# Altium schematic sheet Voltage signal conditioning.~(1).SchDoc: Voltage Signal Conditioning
size 431 x 279 mm; Date: Not shown in title block; ApprovedBy: Not shown in title block; CheckedBy: Not shown in title block; Author: Not shown in title block; CompanyName: Not shown in title block; Engineer: Not shown in title block; Organization: Not shown in title block; Address1: Not shown in title block; Address2: Not shown in title block; Address3: Not shown in title block; Address4: Not shown in title block; DocumentNumber: 4; Revision: Use project parameter SCH_Rev; SheetNumber: 4; SheetTotal: 7; PageSetup: Record=PageOptions|CenterHorizontal=True|CenterVertical=True|PrintScale=1.00|XCorrection=1.00|YCorrection=1.00|PrintKind=0|BorderSize=5000000|LeftOffset=0|BottomOffset=0|Orientation=2|PaperLength=1000|PaperWidth=1000|Scale=100|PaperSource=15|PrintQuality=600|MediaType=1|DitherType=10|PaperKind=Letter|PrintScaleMode=1
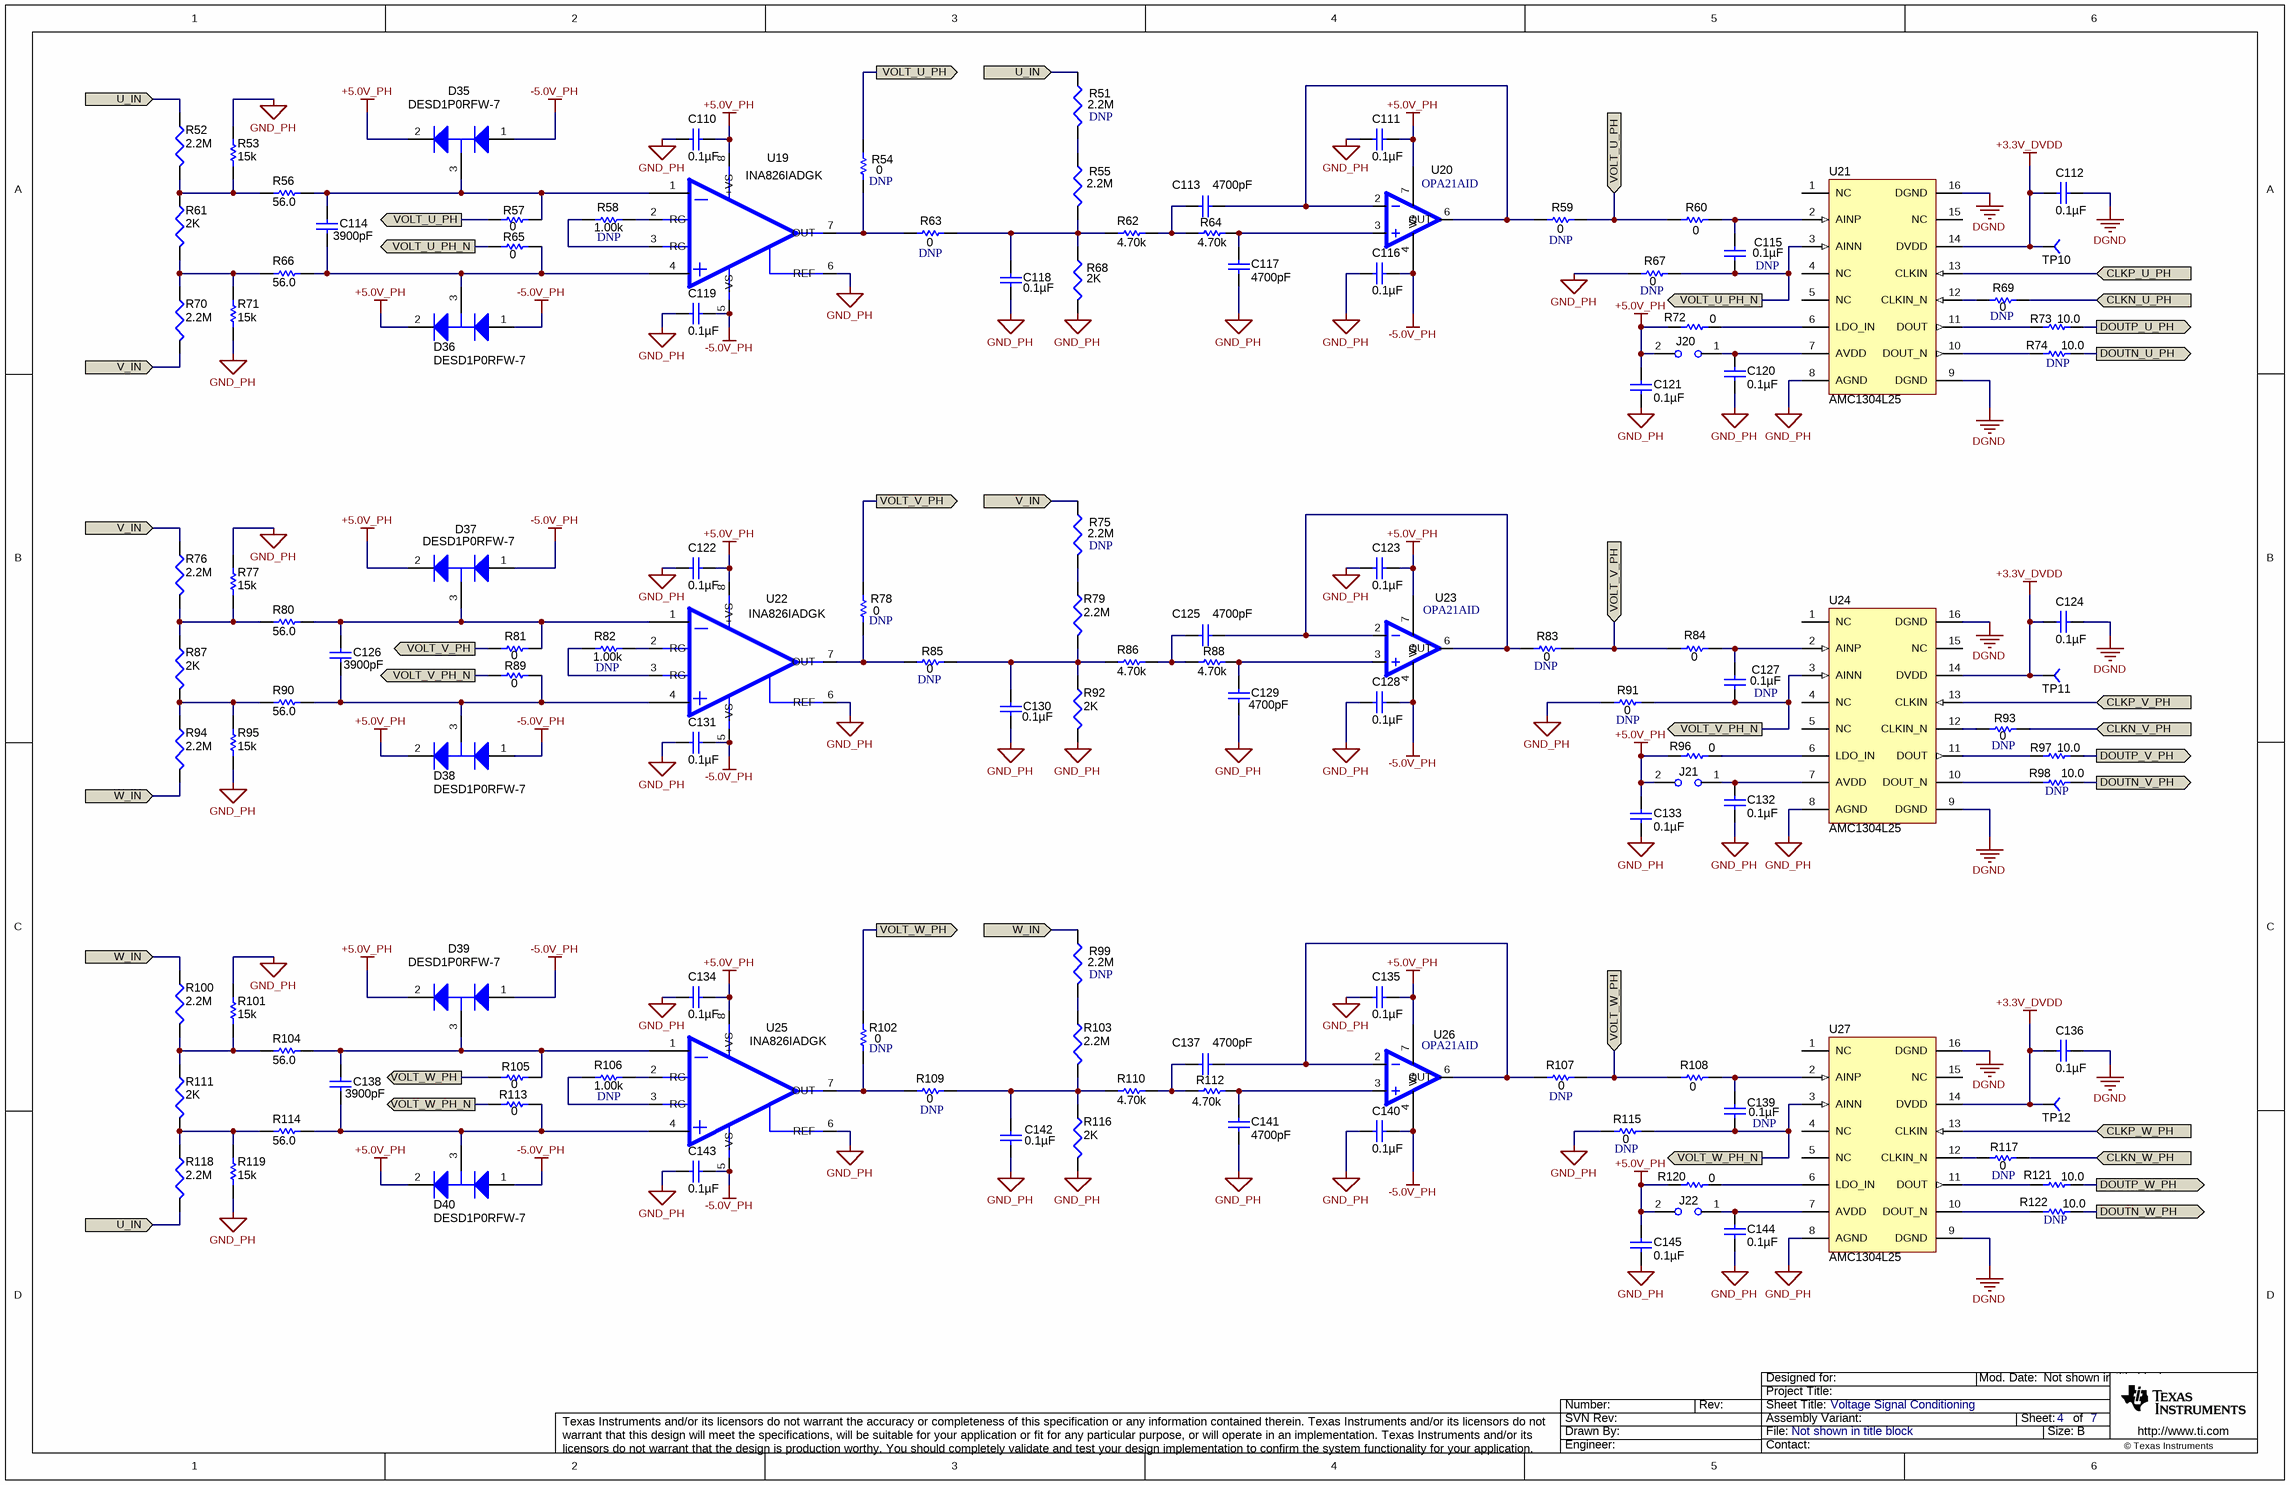
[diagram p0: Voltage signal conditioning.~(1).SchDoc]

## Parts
C110  ValueDisplayed: 0.1µF  [0603]
C111  ValueDisplayed: 0.1µF  [0603]
C112  ValueDisplayed: 0.1µF  [0603]
C113  ValueDisplayed: 4700pF  [0603]
C114  ValueDisplayed: 3900pF  [0603]  (hidden comment: C1608C0G1E392J)
C115  ValueDisplayed: 0.1µF  Not mounted: DNP  [0603]
C116  ValueDisplayed: 0.1µF  [0603]
C117  ValueDisplayed: 4700pF  [0603]
C118  ValueDisplayed: 0.1µF  [0603]
C119  ValueDisplayed: 0.1µF  [0603]
C120  ValueDisplayed: 0.1µF  [0603]
C121  ValueDisplayed: 0.1µF  [0603]
C122  ValueDisplayed: 0.1µF  [0603]
C123  ValueDisplayed: 0.1µF  [0603]
C124  ValueDisplayed: 0.1µF  [0603]
C125  ValueDisplayed: 4700pF  [0603]
C126  ValueDisplayed: 3900pF  [0603]  (hidden comment: C1608C0G1E392J)
C127  ValueDisplayed: 0.1µF  Not mounted: DNP  [0603]
C128  ValueDisplayed: 0.1µF  [0603]
C129  ValueDisplayed: 4700pF  [0603]
C130  ValueDisplayed: 0.1µF  [0603]
C131  ValueDisplayed: 0.1µF  [0603]
C132  ValueDisplayed: 0.1µF  [0603]
C133  ValueDisplayed: 0.1µF  [0603]
C134  ValueDisplayed: 0.1µF  [0603]
C135  ValueDisplayed: 0.1µF  [0603]
C136  ValueDisplayed: 0.1µF  [0603]
C137  ValueDisplayed: 4700pF  [0603]
C138  ValueDisplayed: 3900pF  [0603]  (hidden comment: C1608C0G1E392J)
C139  ValueDisplayed: 0.1µF  Not mounted: DNP  [0603]
C140  ValueDisplayed: 0.1µF  [0603]
C141  ValueDisplayed: 4700pF  [0603]
C142  ValueDisplayed: 0.1µF  [0603]
C143  ValueDisplayed: 0.1µF  [0603]
C144  ValueDisplayed: 0.1µF  [0603]
C145  ValueDisplayed: 0.1µF  [0603]
D35  DESD1P0RFW-7  [SOT-323]
D36  DESD1P0RFW-7  [SOT-323]
D37  DESD1P0RFW-7  [SOT-323]
D38  DESD1P0RFW-7  [SOT-323]
D39  DESD1P0RFW-7  [SOT-323]
D40  DESD1P0RFW-7  [SOT-323]
J20  (no value)  [HDR100_1X2]
J21  (no value)  [HDR100_1X2]
J22  (no value)  [HDR100_1X2]
R51  value 2.2M  Not mounted: DNP  [1210M]
R52  value 2.2M  [1210M]
R53  value 15k  [0603]
R54  value 0  Not mounted: DNP  [0603]
R55  value 2.2M  [1210M]
R56  value 56.0  [0603]  (hidden comment: RC0603FR-0756RL)
R57  value 0  [0603]
R58  value 1.00k  Not mounted: DNP  [0603]
R59  value 0  Not mounted: DNP  [0603]
R60  value 0  [0603]  (hidden comment: CRCW06030000Z0EA)
R61  value 2K  [1210M]
R62  value 4.70k  [0603]
R63  value 0  Not mounted: DNP  [0603]
R64  value 4.70k  [0603]
R65  value 0  [0603]
R66  value 56.0  [0603]  (hidden comment: RC0603FR-0756RL)
R67  value 0  Not mounted: DNP  [0603]
R68  value 2K  [1210M]
R69  value 0  Not mounted: DNP  [0603]
R70  value 2.2M  [1210M]
R71  value 15k  [0603]
R72  value 0  [0603]
R73  value 10.0  [0603]
R74  value 10.0  Not mounted: DNP  [0603]
R75  value 2.2M  Not mounted: DNP  [1210M]
R76  value 2.2M  [1210M]
R77  value 15k  [0603]
R78  value 0  Not mounted: DNP  [0603]
R79  value 2.2M  [1210M]
R80  value 56.0  [0603]  (hidden comment: RC0603FR-0756RL)
R81  value 0  [0603]
R82  value 1.00k  Not mounted: DNP  [0603]
R83  value 0  Not mounted: DNP  [0603]
R84  value 0  [0603]  (hidden comment: CRCW06030000Z0EA)
R85  value 0  Not mounted: DNP  [0603]
R86  value 4.70k  [0603]
R87  value 2K  [1210M]
R88  value 4.70k  [0603]
R89  value 0  [0603]
R90  value 56.0  [0603]  (hidden comment: RC0603FR-0756RL)
R91  value 0  Not mounted: DNP  [0603]
R92  value 2K  [1210M]
R93  value 0  Not mounted: DNP  [0603]
R94  value 2.2M  [1210M]
R95  value 15k  [0603]
R96  value 0  [0603]
R97  value 10.0  [0603]
R98  value 10.0  Not mounted: DNP  [0603]
R99  value 2.2M  Not mounted: DNP  [1210M]
R100  value 2.2M  [1210M]
R101  value 15k  [0603]
R102  value 0  Not mounted: DNP  [0603]
R103  value 2.2M  [1210M]
R104  value 56.0  [0603]  (hidden comment: RC0603FR-0756RL)
R105  value 0  [0603]
R106  value 1.00k  Not mounted: DNP  [0603]
R107  value 0  Not mounted: DNP  [0603]
R108  value 0  [0603]  (hidden comment: CRCW06030000Z0EA)
R109  value 0  Not mounted: DNP  [0603]
R110  value 4.70k  [0603]
R111  value 2K  [1210M]
R112  value 4.70k  [0603]
R113  value 0  [0603]
R114  value 56.0  [0603]  (hidden comment: RC0603FR-0756RL)
R115  value 0  Not mounted: DNP  [0603]
R116  value 2K  [1210M]
R117  value 0  Not mounted: DNP  [0603]
R118  value 2.2M  [1210M]
R119  value 15k  [0603]
R120  value 0  [0603]
R121  value 10.0  [0603]
R122  value 10.0  Not mounted: DNP  [0603]
TP10  (no value)  [TP-040_RND]
TP11  (no value)  [TP-040_RND]
TP12  (no value)  [TP-040_RND]
U19  INA826IADGK  [DGK8]
U20  OPA21AID  [SO8]
U21  AMC1304L25  [DW0016A_N]
U22  INA826IADGK  [DGK8]
U23  OPA21AID  [SO8]
U24  AMC1304L25  [DW0016A_N]
U25  INA826IADGK  [DGK8]
U26  OPA21AID  [SO8]
U27  AMC1304L25  [DW0016A_N]

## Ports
CLKN_U_PH (in), CLKN_V_PH (in), CLKN_W_PH (in), CLKP_U_PH (in), CLKP_V_PH (in), CLKP_W_PH (in), DOUTN_U_PH (out), DOUTN_V_PH (out), DOUTN_W_PH (out), DOUTP_U_PH (out), DOUTP_V_PH (out), DOUTP_W_PH (out), U_IN, V_IN, VOLT_U_PH (in), VOLT_U_PH (out), VOLT_U_PH_N (out), VOLT_V_PH (in), VOLT_V_PH (out), VOLT_V_PH_N (out), VOLT_W_PH (in), VOLT_W_PH (out), VOLT_W_PH_N (out), W_IN

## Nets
+3.3V_DVDD: C112.2 C124.2 C136.2 TP10.1 TP11.1 TP12.1 U21.14(DVDD) U24.14(DVDD) U27.14(DVDD)
+5.0V_PH: C110.2 C111.2 C121.1 C122.2 C123.2 C133.1 C134.2 C135.2 C145.1 D35.2(K) D36.2(K) D37.2(K) D38.2(K) D39.2(K) D40.2(K) J20.2 J21.2 J22.2 R72.1 R96.1 R120.1 U19.8(+VS) U20.7(V+) U22.8(+VS) U23.7(V+) U25.8(+VS) U26.7(V+)
-5.0V_PH: C116.2 C119.2 C128.2 C131.2 C140.2 C143.2 D35.1(A) D36.1(A) D37.1(A) D38.1(A) D39.1(A) D40.1(A) U19.5(-VS) U20.4(V-) U22.5(-VS) U23.4(V-) U25.5(-VS) U26.4(V-)
DGND: C112.1 C124.1 C136.1 U21.9(DGND) U21.16(DGND) U24.9(DGND) U24.16(DGND) U27.9(DGND) U27.16(DGND)
GND_PH: C110.1 C111.1 C116.1 C117.2 C118.1 C119.1 C120.2 C121.2 C122.1 C123.1 C128.1 C129.2 C130.1 C131.1 C132.2 C133.2 C134.1 C135.1 C140.1 C141.2 C142.1 C143.1 C144.2 C145.2 R53.2 R67.2 R68.2 R71.1 R77.2 R91.2 R92.2 R95.1 R101.2 R115.2 R116.2 R119.1 U19.6(REF) U21.8(AGND) U22.6(REF) U24.8(AGND) U25.6(REF) U27.8(AGND)
CLKN_U_PH: R69.2 ; port CLKN_U_PH
CLKN_V_PH: R93.2 ; port CLKN_V_PH
CLKN_W_PH: R117.2 ; port CLKN_W_PH
CLKP_U_PH: U21.13(CLKIN) ; port CLKP_U_PH
CLKP_V_PH: U24.13(CLKIN) ; port CLKP_V_PH
CLKP_W_PH: U27.13(CLKIN) ; port CLKP_W_PH
DOUTN_U_PH: R74.2 ; port DOUTN_U_PH
DOUTN_V_PH: R98.2 ; port DOUTN_V_PH
DOUTN_W_PH: R122.2 ; port DOUTN_W_PH
DOUTP_U_PH: R73.2 ; port DOUTP_U_PH
DOUTP_V_PH: R97.2 ; port DOUTP_V_PH
DOUTP_W_PH: R121.2 ; port DOUTP_W_PH
U_IN: R51.1 R52.1 R118.2 ; port U_IN
V_IN: R70.2 R75.1 R76.1 ; port V_IN
VOLT_U_PH: R54.2 R57.2 R59.2 R60.1 ; port VOLT_U_PH
VOLT_U_PH_N: C115.2 R65.2 R67.1 U21.3(AINN) ; port VOLT_U_PH_N
VOLT_V_PH: R78.2 R81.2 R83.2 R84.1 ; port VOLT_V_PH
VOLT_V_PH_N: C127.2 R89.2 R91.1 U24.3(AINN) ; port VOLT_V_PH_N
VOLT_W_PH: R102.2 R105.2 R107.2 R108.1 ; port VOLT_W_PH
VOLT_W_PH_N: C139.2 R113.2 R115.1 U27.3(AINN) ; port VOLT_W_PH_N
W_IN: R94.2 R99.1 R100.1 ; port W_IN
NetC113_1: C113.1 R62.2 R64.1
NetC113_2: C113.2 R59.1 U20.2 U20.6(OUT)
NetC114_1: C114.1 D35.3(C) R56.2 R57.1 U19.1
NetC114_2: C114.2 D36.3(C) R65.1 R66.2 U19.4
NetC115_1: C115.1 R60.2 U21.2(AINP)
NetC117_1: C117.1 R64.2 U20.3
NetC118_2: C118.2 R55.2 R62.1 R63.2 R68.1
NetC120_1: C120.1 J20.1 U21.7(AVDD)
NetC125_1: C125.1 R86.2 R88.1
NetC125_2: C125.2 R83.1 U23.2 U23.6(OUT)
NetC126_1: C126.1 D37.3(C) R80.2 R81.1 U22.1
NetC126_2: C126.2 D38.3(C) R89.1 R90.2 U22.4
NetC127_1: C127.1 R84.2 U24.2(AINP)
NetC129_1: C129.1 R88.2 U23.3
NetC130_2: C130.2 R79.2 R85.2 R86.1 R92.1
NetC132_1: C132.1 J21.1 U24.7(AVDD)
NetC137_1: C137.1 R110.2 R112.1
NetC137_2: C137.2 R107.1 U26.2 U26.6(OUT)
NetC138_1: C138.1 D39.3(C) R104.2 R105.1 U25.1
NetC138_2: C138.2 D40.3(C) R113.1 R114.2 U25.4
NetC139_1: C139.1 R108.2 U27.2(AINP)
NetC141_1: C141.1 R112.2 U26.3
NetC142_2: C142.2 R103.2 R109.2 R110.1 R116.1
NetC144_1: C144.1 J22.1 U27.7(AVDD)
NetR51_2: R51.2 R55.1
NetR52_2: R52.2 R53.1 R56.1 R61.1
NetR54_1: R54.1 R63.1 U19.7(OUT)
NetR58_1: R58.1 U19.3(RG)
NetR58_2: R58.2 U19.2(RG)
NetR61_2: R61.2 R66.1 R70.1 R71.2
NetR69_1: R69.1 U21.12(CLKIN_N)
NetR72_2: R72.2 U21.6(LDO_IN)
NetR73_1: R73.1 U21.11(DOUT)
NetR74_1: R74.1 U21.10(DOUT_N)
NetR75_2: R75.2 R79.1
NetR76_2: R76.2 R77.1 R80.1 R87.1
NetR78_1: R78.1 R85.1 U22.7(OUT)
NetR82_1: R82.1 U22.3(RG)
NetR82_2: R82.2 U22.2(RG)
NetR87_2: R87.2 R90.1 R94.1 R95.2
NetR93_1: R93.1 U24.12(CLKIN_N)
NetR96_2: R96.2 U24.6(LDO_IN)
NetR97_1: R97.1 U24.11(DOUT)
NetR98_1: R98.1 U24.10(DOUT_N)
NetR99_2: R99.2 R103.1
NetR100_2: R100.2 R101.1 R104.1 R111.1
NetR102_1: R102.1 R109.1 U25.7(OUT)
NetR106_1: R106.1 U25.3(RG)
NetR106_2: R106.2 U25.2(RG)
NetR111_2: R111.2 R114.1 R118.1 R119.2
NetR117_1: R117.1 U27.12(CLKIN_N)
NetR120_2: R120.2 U27.6(LDO_IN)
NetR121_1: R121.1 U27.11(DOUT)
NetR122_1: R122.1 U27.10(DOUT_N)

Not connected (* = marked no-connect by the designer): U21 1(NC) 4(NC) 5(NC) 15(NC); U24 1(NC) 4(NC) 5(NC) 15(NC); U27 1(NC) 4(NC) 5(NC) 15(NC)

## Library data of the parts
C110 C111 C115 C116 C118-C123 C127 C128 C130-C135 C139 C140 C142-C145 = C0603C104K5RACTU: CAP, CERM, 0.1uF, 50V, +/-10%, X7R, 0603; Manufacturer: Kemet; Polarized: N; CompType: Capacitor; U/M: EA; Cap_F: 0.0000001; Tolerance_%: 10; Value1: Unknown; VDC_V: 50; TaMin_C: -55; TaMax_C: 125
C112 C124 C136 = 06033C104JAT2A: CAP, CERM, 0.1uF, 25V, +/-5%, X7R, 0603; Manufacturer: AVX; Polarized: N; CompType: Capacitor; U/M: EA; Cap_F: 0.0000001; Tolerance_%: 5; ESR_Ohm: 0.05; Value1: 0.05 ohm; VDC_V: 25; TaMin_C: -55; TaMax_C: 125
C113 C117 C125 C129 C137 C141 = 06031C472KAT2A: CAP, CERM, 4700pF, 100V, +/-10%, X7R, 0603; Manufacturer: AVX; Polarized: N; CompType: Capacitor; U/M: EA; Cap_F: 0.0000000047; Tolerance_%: 10; ESR_Ohm: 0.136; Value1: 0.136 ohm; VDC_V: 100; TaMin_C: -55; TaMax_C: 125
C114 C126 C138 = C1608C0G1E392J: CAP, CERM, 3900pF, 25V, +/-5%, C0G/NP0, 0603; Manufacturer: TDK; Polarized: N; CompType: Capacitor; U/M: EA; Cap_F: 0.0000000039; Tolerance_%: 5; Value1: Unknown; VDC_V: 25; TaMin_C: -55; TaMax_C: 125
D35-D40 = BAV99WT1G: Diode, P-N, 70V, 0.2A, SOT-323; Manufacturer: Diodes Inc; Value: DNP
J20-J22 = JUMPER_2X100MIL: Header, Male 2-pin, 100mil spacing,; Manufacturer: Sullins; PartNumber: PEC02SAAN; area: 20000; Value: PEC02SAAN
R51 R52 R55 R70 R75 R76 R79 R94 R99 R100 R103 R118 = RES_KTR25JZPF2204: RES 2.2M OHM 1/3W 1% 1210; Manufacturer: Rohm Semiconductor; CompType: Resistor
R53 R71 R77 R95 R101 R119 = RC0603FR-0747KL: RES 15.0K OHM 1/10W .1% SMD 0603; PartNumber: RT0603BRD0715KL-ND; Manufacturer: Yageo America; CompType: Resistor; Res_ohm: 15000; Value_Code: 15k0; Tolerance_%: 1; Power_W: 0.1; Value2: 0.1W; VDC_V: 150; TempCo: 25ppm/C; U/M: EA
R54 R57 R59 R60 R63 R65 R67 R69 R72 R78 R81 R83-R85 R89 R91 R93 R96 R102 R105 R107-R109 R113 R115 R117 R120 = CRCW06030000Z0EA: RES, 0 ohm, 5%, 0.1W, 0603; Manufacturer: Vishay-Dale; CompType: Resistor; Value_Code: 0000; Tolerance_%: 5; Power_W: 0.1; VDC_V: 75; TempCo: 200 ppm/C; EIA_Code: E24; U/M: EA
R56 R66 R80 R90 R104 R114 = RC0603FR-0756RL: RES, 56.0 ohm, 1%, 0.1W, 0603; Manufacturer: Yageo America; CompType: Resistor; Res_ohm: 56; Value_Code: 56R0; Tolerance_%: 1; Power_W: 0.1; VDC_V: 150; TempCo: 200 ppm/C; U/M: EA
R58 R82 R106 = RC0603FR-071KL: RES, 1.00k ohm, 1%, 0.1W, 0603; Manufacturer: Yageo America; CompType: Resistor; Res_ohm: 1000; Value_Code: 1k00; Tolerance_%: 1; Power_W: 0.1; VDC_V: 150; TempCo: 200 ppm/C; EIA_Code: E96; U/M: EA
R61 R68 R87 R92 R111 R116 = RES_KTR25JZPF2001: RES 2K OHM 1/3W 1% 1210; Manufacturer: Rohm Semiconductor; CompType: Resistor
R62 R64 R86 R88 R110 R112 = RC0603FR-074K7L: RES, 4.70k ohm, 1%, 0.1W, 0603; Manufacturer: Yageo America; CompType: Resistor; Res_ohm: 4700; Value_Code: 4k70; Tolerance_%: 1; Power_W: 0.1; VDC_V: 150; TempCo: 200 ppm/C; U/M: EA
R73 R74 R97 R98 R121 R122 = CRCW060310R0FKEA: RES, 10.0 ohm, 1%, 0.1W, 0603; Manufacturer: Vishay-Dale; CompType: Resistor; Res_ohm: 10; Value_Code: 10R0; Tolerance_%: 1; Power_W: 0.1; VDC_V: 75; TempCo: 100 ppm/C; EIA_Code: E96; U/M: EA
TP10-TP12 = TP-040_RND: Test Point, O.040 Hole; Manufacturer: STD; Value: STD
U19 U22 U25 = INA826IADGK: IC, Precision, 200uA, 36V Supply Instrument Amplifier.; Manufacturer: TI; Alternate Manufacturer: None; Area: 35250
U20 U23 U26 = OPA211AID: IC, 1.1nV/vHz Noise, Low Power, Precision OpAmp; PartNumber: OPA211ID; Manufacturer: TI; Alternate Manufacturer: None; Area: 75900; Value: OPA211ID
U21 U24 U27 = AMC1304L25: 20 MHz, Isolated Delta-Sigma Modulator, LVDS interface:; Alternate Manufacturer: None; Manufacturer: Texas Instruments; SymbolCreator: x0120606; CompType: IC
